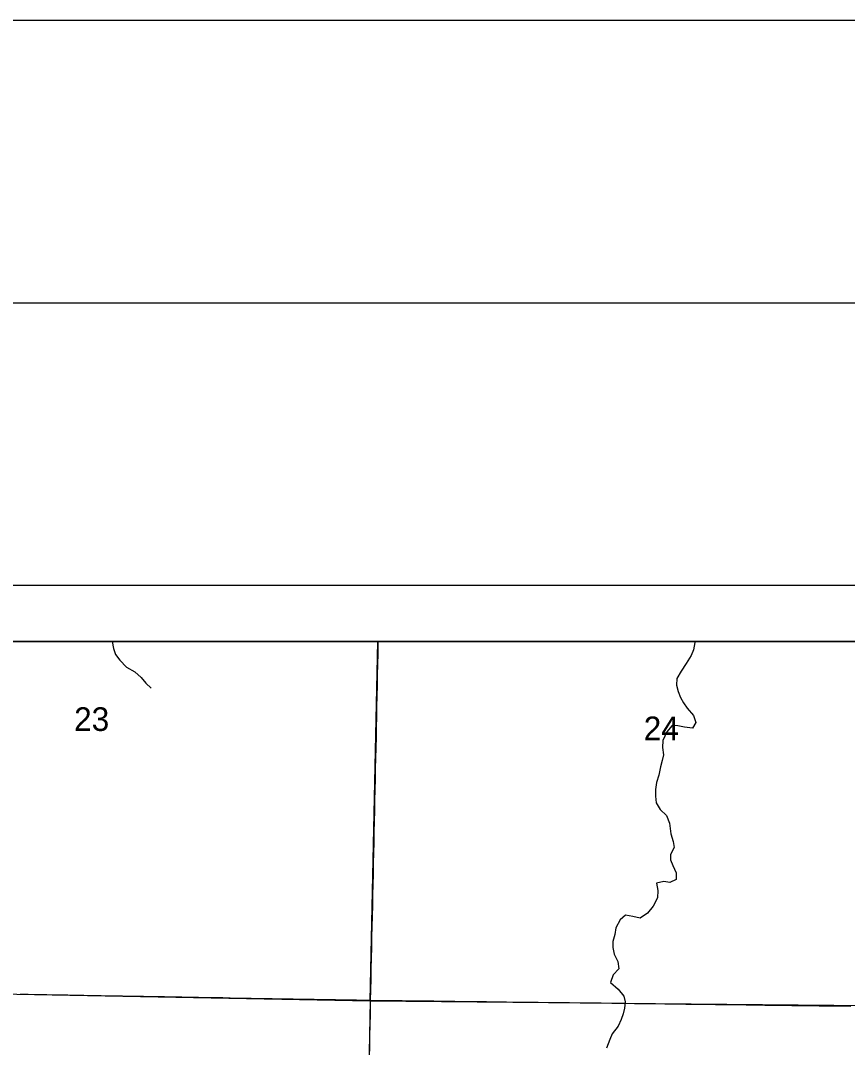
# Model space of a CAD drawing. Extents: x -11.1 to 34, y -3.9 to 22.
# Drawn here: x 5.806 to 7.271, y 20.181 to 22 of the extents above; entities that cross this region are included whole.
import ezdxf

# ---------------------------------------------------------------- set-up
doc = ezdxf.new("R2010")
doc.units = 0
for name, color, linetype in [('GM_X_Corporation', 7, 'Continuous'), ('GM_X_County_Road', 7, 'Continuous'), ('GM_X_Minor_River', 7, 'Continuous'), ('GM_X_Section_Text', 7, 'Continuous'), ('GM_X_State_Route', 7, 'Continuous'), ('SH_Border', 7, 'Continuous'), ('SH_Cut_Line', 7, 'Continuous'), ('SH_Data', 7, 'Continuous')]:
    doc.layers.add(name, color=color, linetype=linetype)

msp = doc.modelspace()

# ---------------------------------------------------------------- linework, layer by layer
at = {"layer": 'GM_X_Corporation'}
for points in [[(8.9, 20.9), (2.1, 20.9), (2.1, 14.1), (7.332, 14.1)], [(7.452, 20.9), (2.1, 20.9), (2.1, 18.3243), (2.3663, 18.3195), (2.386, 18.3192), (3.3765, 18.301), (3.3885, 18.301), (4.3933, 18.2849), (4.8079, 18.2783), (5.3973, 18.2661), (6.2873, 18.2553), (6.3214, 18.2549), (6.5234, 18.2515), (7.399, 18.2383)]]:
    msp.add_lwpolyline(points, dxfattribs=at)
for points in [[(6.4389, 20.9), (5.4337, 20.9), (5.4232, 20.283), (6.4249, 20.2637)], [(7.4509, 20.9), (6.4389, 20.9), (6.4249, 20.2637), (7.4361, 20.2547), (7.4373, 20.2744)], [(5.4232, 20.283), (6.4249, 20.2637), (6.4054, 19.2568), (5.4044, 19.2723)]]:
    msp.add_lwpolyline(points, close=True, dxfattribs=at)
at = {"layer": 'GM_X_County_Road'}
msp.add_lwpolyline([(6.424, 20.1649), (6.4244, 20.1835), (6.4248, 20.2021), (6.4251, 20.2208), (6.4255, 20.2394), (6.4258, 20.2521), (6.426, 20.2649), (6.4264, 20.2835), (6.4268, 20.3022), (6.4272, 20.3208), (6.4276, 20.3394), (6.428, 20.3581), (6.4284, 20.3767), (6.4288, 20.3954), (6.4292, 20.414), (6.4296, 20.4326), (6.43, 20.4513), (6.4304, 20.4699), (6.4308, 20.4885), (6.4312, 20.5072), (6.4316, 20.5258), (6.432, 20.5444), (6.4324, 20.5631), (6.4328, 20.5817), (6.4332, 20.6003), (6.4337, 20.619), (6.434, 20.6376), (6.4345, 20.6562), (6.4348, 20.6749), (6.4353, 20.6935), (6.4357, 20.7121), (6.4361, 20.7308), (6.4364, 20.7486), (6.4368, 20.7665), (6.4372, 20.7851), (6.4376, 20.8037), (6.438, 20.8224), (6.4384, 20.841), (6.4388, 20.8596), (6.4392, 20.8783), (6.4396, 20.8969), (6.4397, 20.9)], dxfattribs=at)
at = {"layer": 'GM_X_Minor_River'}
for points in [[(5.968, 20.9), (5.9703, 20.8878), (5.9742, 20.8774), (5.9816, 20.867), (5.9935, 20.8546), (6.0081, 20.8463), (6.0196, 20.8366), (6.0274, 20.8266), (6.0374, 20.8176)], [(7.0004, 20.9), (7.0002, 20.8987), (6.998, 20.8858)], [(6.998, 20.8858), (6.994, 20.8756), (6.985, 20.8614), (6.9759, 20.848), (6.9684, 20.8348), (6.9682, 20.8227), (6.971, 20.8116), (6.9749, 20.8013), (6.9804, 20.7917), (6.9867, 20.7821), (6.9978, 20.7693), (7.002, 20.7567), (6.9961, 20.7466), (6.9821, 20.7484), (6.9704, 20.7509), (6.9602, 20.7515), (6.9508, 20.74), (6.9437, 20.725), (6.943, 20.7128), (6.945, 20.6995), (6.9425, 20.6897), (6.9393, 20.6784), (6.9367, 20.6636), (6.9326, 20.6508), (6.9308, 20.6383), (6.9306, 20.6262), (6.9318, 20.6144), (6.9388, 20.6025), (6.9503, 20.5924), (6.9557, 20.5786)], [(6.9557, 20.5786), (6.9577, 20.5594), (6.9619, 20.546), (6.9636, 20.5357), (6.9572, 20.5233), (6.9573, 20.5138), (6.9612, 20.5035), (6.9673, 20.4908), (6.9674, 20.4787), (6.9562, 20.4736), (6.9453, 20.4751), (6.9327, 20.472), (6.935, 20.459), (6.9343, 20.4465), (6.9263, 20.4315), (6.9168, 20.4189), (6.9037, 20.4101), (6.8905, 20.4135), (6.8777, 20.4157), (6.868, 20.4073), (6.8604, 20.393), (6.8586, 20.3813), (6.8552, 20.3689), (6.8549, 20.3586), (6.8576, 20.3468), (6.8641, 20.3337), (6.8657, 20.3208), (6.8559, 20.31), (6.851, 20.2965), (6.8647, 20.2844), (6.8746, 20.272), (6.8767, 20.2624), (6.8756, 20.2511), (6.8734, 20.2409), (6.8701, 20.2311), (6.8645, 20.2191), (6.8539, 20.2057), (6.8495, 20.1956), (6.8438, 20.1802)]]:
    msp.add_lwpolyline(points, dxfattribs=at)
at = {"layer": 'GM_X_State_Route'}
msp.add_lwpolyline([(5.8052, 20.2758), (5.8193, 20.2755), (5.8333, 20.2753), (5.8427, 20.2751), (5.852, 20.275), (5.8707, 20.2746), (5.8893, 20.2743), (5.9079, 20.274), (5.918, 20.2738), (5.9281, 20.2736), (5.9384, 20.2734), (5.9488, 20.2732), (5.9674, 20.2729), (5.9861, 20.2726), (6.0047, 20.2723), (6.0233, 20.2719), (6.042, 20.2716), (6.0606, 20.2713), (6.0761, 20.271), (6.0916, 20.2708), (6.1102, 20.2704), (6.1212, 20.2702), (6.1323, 20.27), (6.1509, 20.2697), (6.164, 20.2695), (6.1771, 20.2693), (6.1957, 20.2689), (6.2144, 20.2686), (6.233, 20.2683), (6.2516, 20.268), (6.2703, 20.2676), (6.2889, 20.2673), (6.3076, 20.267), (6.3262, 20.2667), (6.3448, 20.2663), (6.3635, 20.266), (6.3821, 20.2657), (6.4008, 20.2654), (6.4134, 20.2651), (6.426, 20.2649), (6.4447, 20.2647), (6.4633, 20.2645), (6.4819, 20.2642), (6.5006, 20.264), (6.5192, 20.2638), (6.5379, 20.2636), (6.5565, 20.2633), (6.5752, 20.2631), (6.5938, 20.2629), (6.6124, 20.2627), (6.6311, 20.2625), (6.6489, 20.2623), (6.6667, 20.262), (6.6853, 20.2618), (6.704, 20.2616), (6.7226, 20.2614), (6.7412, 20.2612), (6.7599, 20.2609), (6.7785, 20.2607), (6.7972, 20.2605), (6.8158, 20.2603), (6.8345, 20.2601), (6.8531, 20.2598), (6.8651, 20.2597), (6.8772, 20.2595), (6.8937, 20.2594), (6.9102, 20.2592), (6.9284, 20.2589), (6.9471, 20.2587), (6.9657, 20.2585), (6.9844, 20.2582), (7.003, 20.258), (7.0217, 20.2578), (7.0368, 20.2576), (7.052, 20.2574), (7.0646, 20.2573), (7.0771, 20.2571), (7.0914, 20.2569), (7.1056, 20.2567), (7.1242, 20.2565), (7.1428, 20.2563), (7.1615, 20.2561), (7.1724, 20.2559), (7.1833, 20.2558), (7.202, 20.2556), (7.2206, 20.2553), (7.2393, 20.2551), (7.2579, 20.2549), (7.2766, 20.2546)], dxfattribs=at)
at = {"layer": 'SH_Border'}
msp.add_lwpolyline([(1.5, 21.5), (33.5, 21.5), (33.5, 0.5), (1.5, 0.5)], close=True, dxfattribs=at)
at = {"layer": 'SH_Cut_Line'}
msp.add_lwpolyline([(0, 0), (34, 0), (34, 22), (0, 22)], close=True, dxfattribs=at)
at = {"layer": 'SH_Data'}
for p, q in [((2, 21), (9, 21)), ((2.1, 20.9), (8.9, 20.9))]:
    msp.add_line(p, q, dxfattribs=at)

# ---------------------------------------------------------------- texts
at = {"layer": 'GM_X_Section_Text'}
for s, p in [('23', (5.9006, 20.7419)), ('24', (6.9098, 20.7255))]:
    msp.add_text(s, height=0.04186, rotation=0, dxfattribs=at).set_placement(p)

doc.saveas('drawing.dxf')
